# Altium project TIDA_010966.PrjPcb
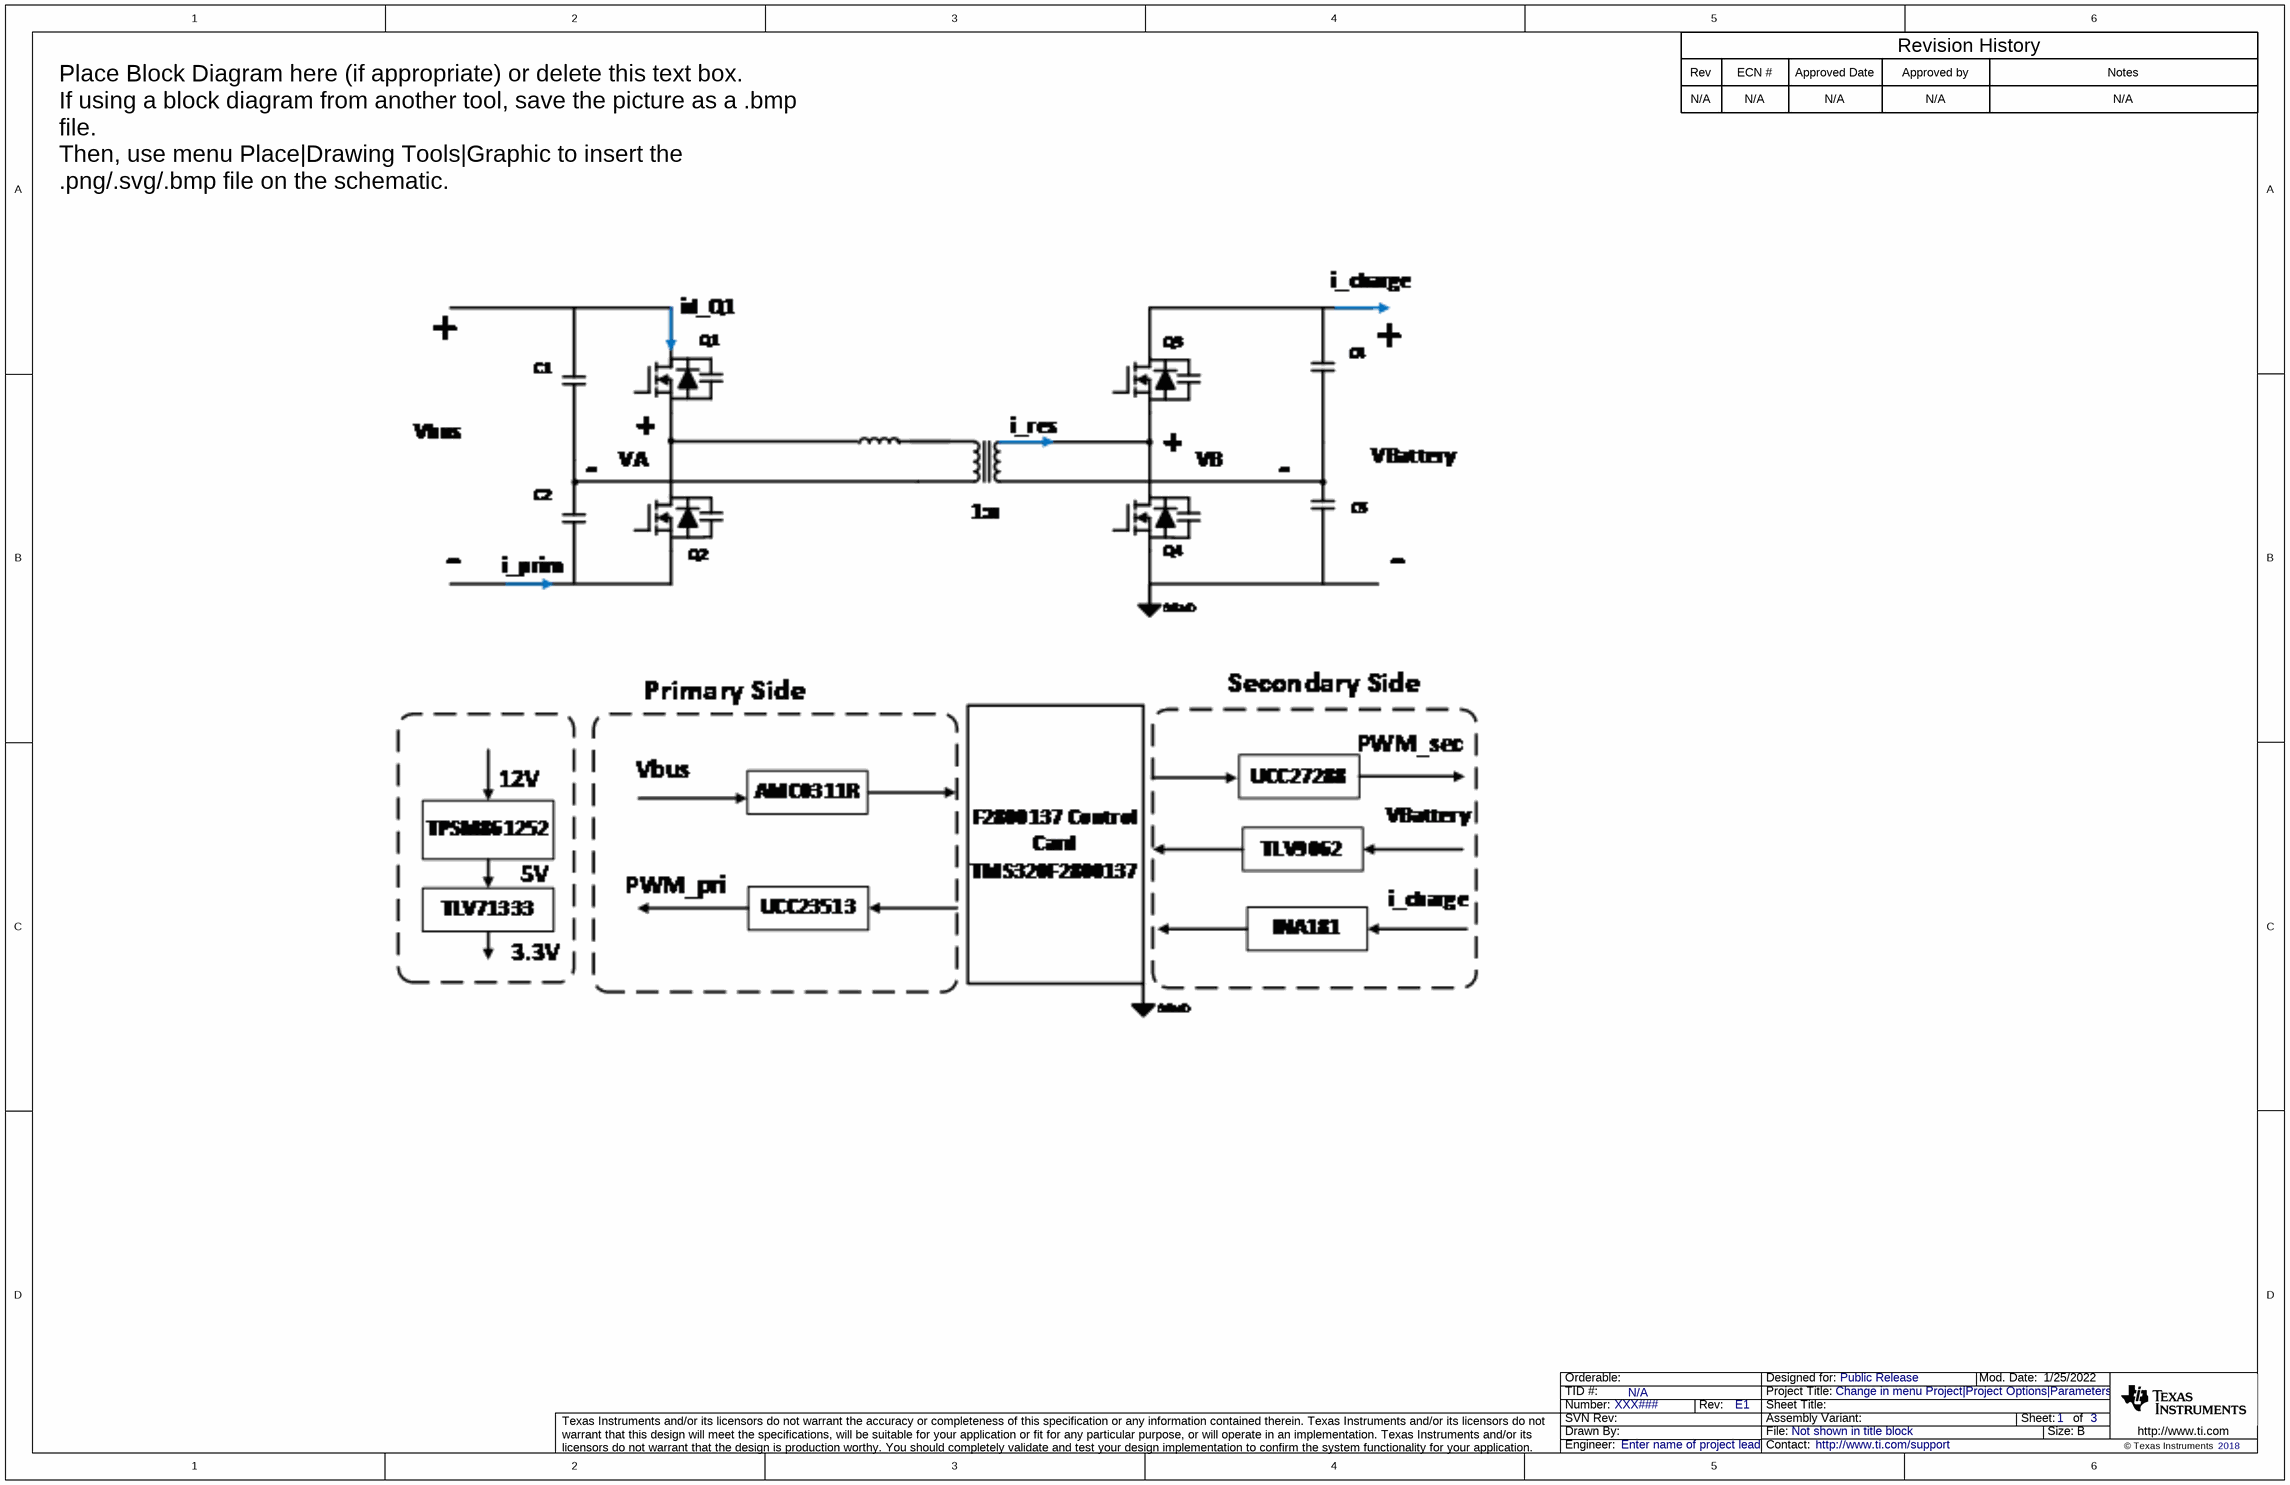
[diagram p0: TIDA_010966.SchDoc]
CopyrightYear: 2018; PCB_Layout: Who did the Layout?; PCB_Rev: E1; PRJ_Customer: Public Release; PRJ_Engineer: Enter name of project lead; PRJ_Number: XXX###; PRJ_Title: Change in menu Project|Project Options|Parameters; SCH_Rev: E1; TechSupport: http://www.ti.com/support; TID: N/A
2 sheets, 120 parts. Net scope: flat (ports and power ports of the same name join across sheets).
Board file: TIDA_010966.PcbDoc
Sheets:
  TIDA_010966.SchDoc
  TIDA_010966_BlankSheet.SchDoc

## Sheet TIDA_010966.SchDoc
size 431 x 279 mm; Date: Not shown in title block; ApprovedBy: Not shown in title block; CheckedBy: Not shown in title block; Author: Not shown in title block; CompanyName: Not shown in title block; Engineer: Not shown in title block; Organization: Not shown in title block; Address1: Not shown in title block; Address2: Not shown in title block; Address3: Not shown in title block; Address4: Not shown in title block; DocumentNumber: 1; Revision: Use project parameter SCH_Rev; SheetNumber: 1; SheetTotal: 3; PageSetup: Record=PageOptions¦CenterHorizontal=True¦CenterVertical=True¦PrintScale=1.00¦XCorrection=1.00¦YCorrection=1.00¦PrintKind=0¦BorderSize=5000000¦LeftOffset=0¦BottomOffset=0¦Orientation=2¦PaperLength=1000¦PaperWidth=1000¦Scale=100¦PaperSource=15¦PrintQuality=600¦MediaType=1¦DitherType=10¦PaperKind=Letter¦PrintScaleMode=1

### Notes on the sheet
- Rev
- N/A
- ECN #
- Approved Date
- Approved by
- Revision History
- Notes
- Place Block Diagram here (if appropriate) or delete this text box.
  If using a block diagram from another tool, save the picture as a .bmp file.
  Then, use menu Place|Drawing Tools|Graphic to insert the .png/.svg/.bmp file on the schematic.

## Sheet TIDA_010966_BlankSheet.SchDoc
size A2; Date: Not shown in title block; ApprovedBy: Not shown in title block; CheckedBy: Not shown in title block; Author: Not shown in title block; CompanyName: Not shown in title block; Engineer: Not shown in title block; Organization: Not shown in title block; Address1: Not shown in title block; Address2: Not shown in title block; Address3: Not shown in title block; Address4: Not shown in title block; DocumentNumber: 2; Revision: Use project parameter SCH_Rev; SheetNumber: 2; SheetTotal: 3; PageSetup: Record=PageOptions¦CenterHorizontal=True¦CenterVertical=True¦PrintScale=1.00¦XCorrection=1.00¦YCorrection=1.00¦PrintKind=0¦BorderSize=5000000¦LeftOffset=0¦BottomOffset=0¦Orientation=2¦PaperLength=1000¦PaperWidth=1000¦Scale=100¦PaperSource=15¦PrintQuality=600¦MediaType=1¦DitherType=10¦PaperKind=Letter¦PrintScaleMode=1
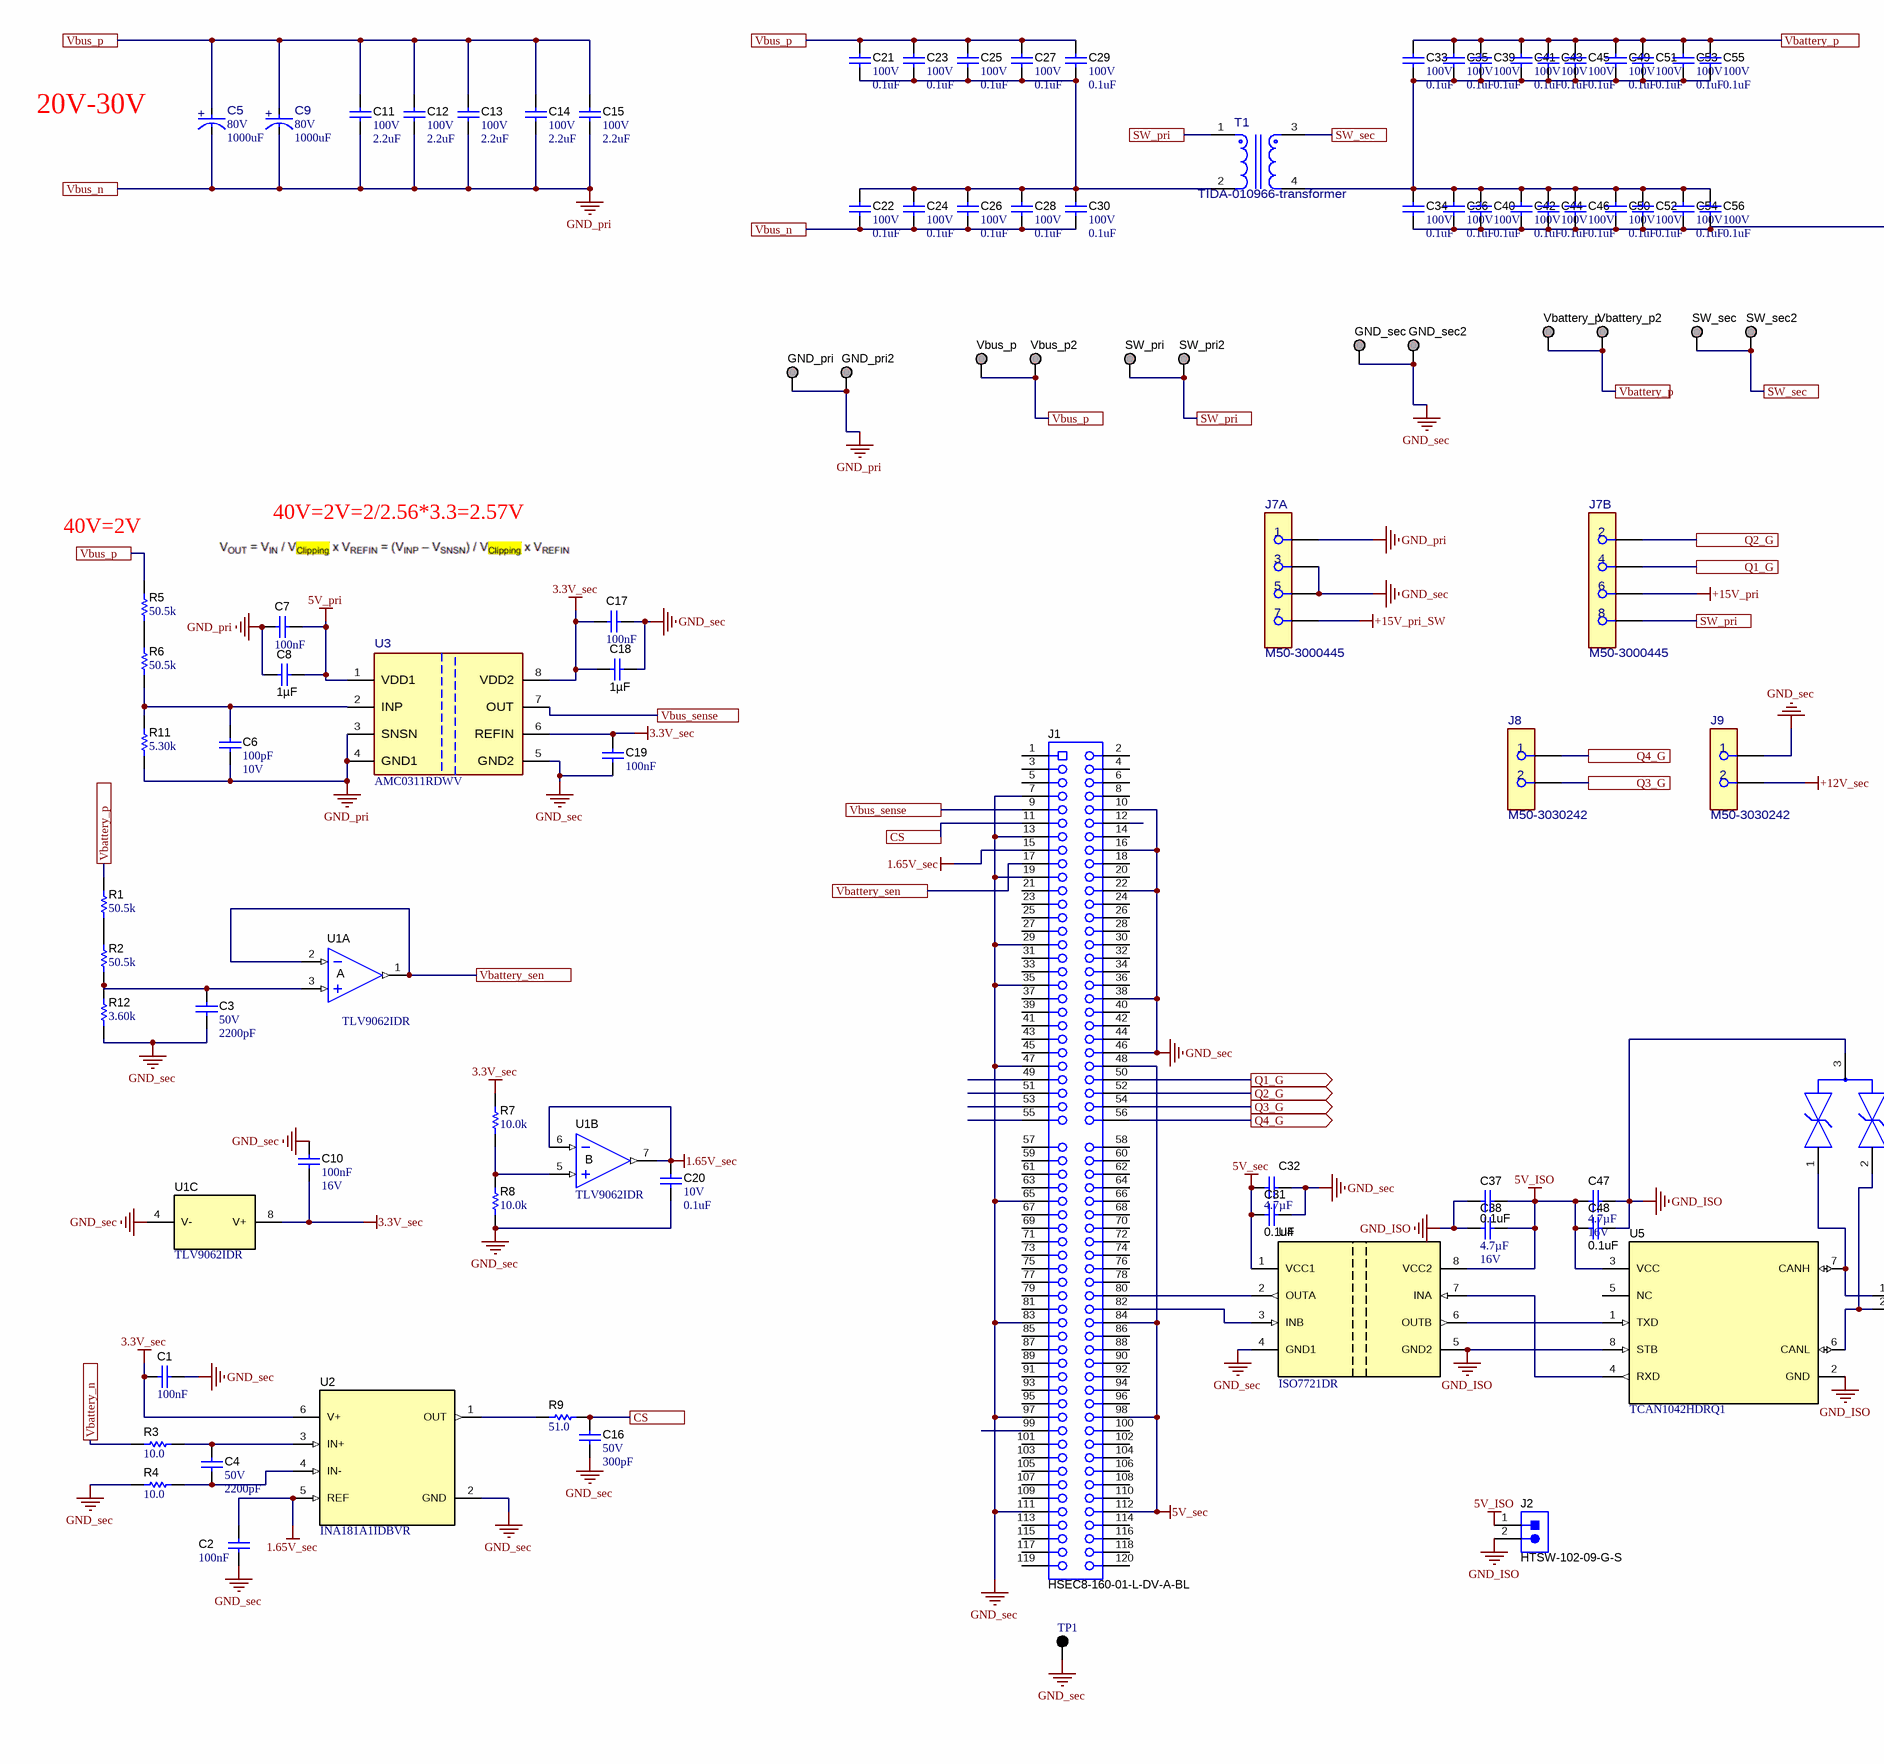
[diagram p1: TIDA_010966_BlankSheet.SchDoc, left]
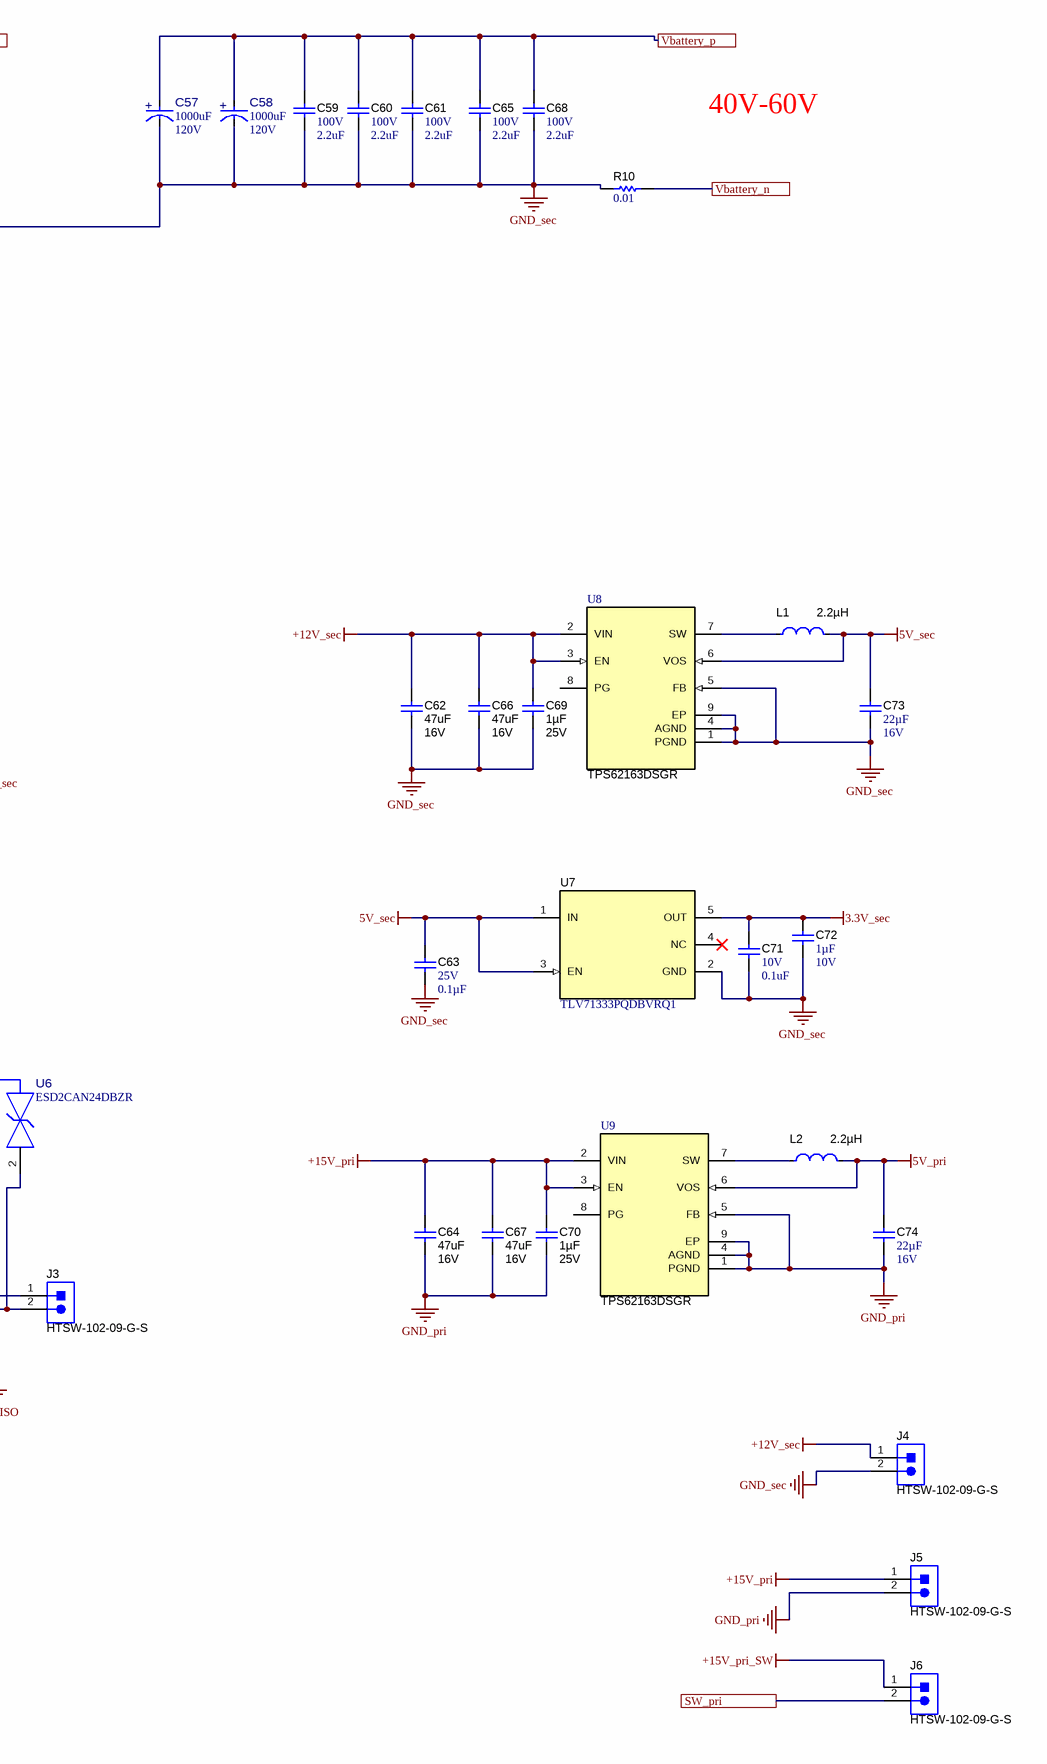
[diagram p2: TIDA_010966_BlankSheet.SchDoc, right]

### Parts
C1  Cap_F: 100nF  [0603]  (hidden comment: CGA3E2X7R1E104K080AA)
C2  ValueDisplayed: 100nF  [0603]  (hidden comment: GRM1885C1H301JA01D)
C3  VDC_V: 50V  ValueDisplayed: 2200pF  [0603]  (hidden comment: GRM1885C1H222JA01D)
C4  VDC_V: 50V  ValueDisplayed: 2200pF  [0603]  (hidden comment: GRM1885C1H222JA01D)
C5  VDC_V: 80V  ValueDisplayed: 1000uF  [FP-EGPD800ELL102ML35H_RADIAL-MFG]  (hidden comment: EGPD800ELL102ML35H)
C6  Cap_F: 100pF  VDC_V: 10V  [0603]  (hidden comment: 0603ZC101KAT2A)
C7  ValueDisplayed: 100nF  [0603]  (hidden comment: GRM1885C1H301JA01D)
C8  Cap_F: 1µF  [0805_HV]  (hidden comment: C0805C105K3RACTU)
C9  VDC_V: 80V  ValueDisplayed: 1000uF  [FP-EGPD800ELL102ML35H_RADIAL-MFG]  (hidden comment: EGPD800ELL102ML35H)
C10  Cap_F: 100nF  VDC_V: 16V  [0603]  (hidden comment: GRM188R71C104KA01D)
C11  VDC_V: 100V  ValueDisplayed: 2.2uF  [1206_180]  (hidden comment: CGA5L3X7S2A225K160AB)
C12  VDC_V: 100V  ValueDisplayed: 2.2uF  [1206_180]  (hidden comment: CGA5L3X7S2A225K160AB)
C13  VDC_V: 100V  ValueDisplayed: 2.2uF  [1206_180]  (hidden comment: CGA5L3X7S2A225K160AB)
C14  VDC_V: 100V  ValueDisplayed: 2.2uF  [1206_180]  (hidden comment: CGA5L3X7S2A225K160AB)
C15  VDC_V: 100V  ValueDisplayed: 2.2uF  [1206_180]  (hidden comment: CGA5L3X7S2A225K160AB)
C16  VDC_V: 50V  ValueDisplayed: 300pF  [0603]  (hidden comment: GRM1885C1H301JA01D)
C17  ValueDisplayed: 100nF  [0603]  (hidden comment: GRM1885C1H301JA01D)
C18  Cap_F: 1µF  [0805_HV]  (hidden comment: C0805C105K3RACTU)
C19  ValueDisplayed: 100nF  [0603]  (hidden comment: GRM1885C1H301JA01D)
C20  VDC_V: 10V  ValueDisplayed: 0.1uF  [0402]  (hidden comment: C1005X5R1A104K050BA)
C21  VDC_V: 100V  ValueDisplayed: 0.1uF  [1206_190]  (hidden comment: C3216C0G2A104J160AC)
C22  VDC_V: 100V  ValueDisplayed: 0.1uF  [1206_190]  (hidden comment: C3216C0G2A104J160AC)
C23  VDC_V: 100V  ValueDisplayed: 0.1uF  [1206_190]  (hidden comment: C3216C0G2A104J160AC)
C24  VDC_V: 100V  ValueDisplayed: 0.1uF  [1206_190]  (hidden comment: C3216C0G2A104J160AC)
C25  VDC_V: 100V  ValueDisplayed: 0.1uF  [1206_190]  (hidden comment: C3216C0G2A104J160AC)
C26  VDC_V: 100V  ValueDisplayed: 0.1uF  [1206_190]  (hidden comment: C3216C0G2A104J160AC)
C27  VDC_V: 100V  ValueDisplayed: 0.1uF  [1206_190]  (hidden comment: C3216C0G2A104J160AC)
C28  VDC_V: 100V  ValueDisplayed: 0.1uF  [1206_190]  (hidden comment: C3216C0G2A104J160AC)
C29  VDC_V: 100V  ValueDisplayed: 0.1uF  [1206_190]  (hidden comment: C3216C0G2A104J160AC)
C30  VDC_V: 100V  ValueDisplayed: 0.1uF  [1206_190]  (hidden comment: C3216C0G2A104J160AC)
C31  ValueDisplayed: 0.1uF  [0402]  (hidden comment: 0402YC104KAT2A)
C32  Cap_F: 4.7µF  [0603]  (hidden comment: GRM188Z71C475KE21D)
C33  VDC_V: 100V  ValueDisplayed: 0.1uF  [1206_190]  (hidden comment: C3216C0G2A104J160AC)
C34  VDC_V: 100V  ValueDisplayed: 0.1uF  [1206_190]  (hidden comment: C3216C0G2A104J160AC)
C35  VDC_V: 100V  ValueDisplayed: 0.1uF  [1206_190]  (hidden comment: C3216C0G2A104J160AC)
C36  VDC_V: 100V  ValueDisplayed: 0.1uF  [1206_190]  (hidden comment: C3216C0G2A104J160AC)
C37  ValueDisplayed: 0.1uF  [0402]  (hidden comment: 0402YC104KAT2A)
C38  Cap_F: 4.7µF  VDC_V: 16V  [0603]  (hidden comment: GRM188Z71C475KE21D)
C39  VDC_V: 100V  ValueDisplayed: 0.1uF  [1206_190]  (hidden comment: C3216C0G2A104J160AC)
C40  VDC_V: 100V  ValueDisplayed: 0.1uF  [1206_190]  (hidden comment: C3216C0G2A104J160AC)
C41  VDC_V: 100V  ValueDisplayed: 0.1uF  [1206_190]  (hidden comment: C3216C0G2A104J160AC)
C42  VDC_V: 100V  ValueDisplayed: 0.1uF  [1206_190]  (hidden comment: C3216C0G2A104J160AC)
C43  VDC_V: 100V  ValueDisplayed: 0.1uF  [1206_190]  (hidden comment: C3216C0G2A104J160AC)
C44  VDC_V: 100V  ValueDisplayed: 0.1uF  [1206_190]  (hidden comment: C3216C0G2A104J160AC)
C45  VDC_V: 100V  ValueDisplayed: 0.1uF  [1206_190]  (hidden comment: C3216C0G2A104J160AC)
C46  VDC_V: 100V  ValueDisplayed: 0.1uF  [1206_190]  (hidden comment: C3216C0G2A104J160AC)
C47  Cap_F: 4.7µF  VDC_V: 16V  [0603]  (hidden comment: GRM188Z71C475KE21D)
C48  ValueDisplayed: 0.1uF  [0402]  (hidden comment: 0402YC104KAT2A)
C49  VDC_V: 100V  ValueDisplayed: 0.1uF  [1206_190]  (hidden comment: C3216C0G2A104J160AC)
C50  VDC_V: 100V  ValueDisplayed: 0.1uF  [1206_190]  (hidden comment: C3216C0G2A104J160AC)
C51  VDC_V: 100V  ValueDisplayed: 0.1uF  [1206_190]  (hidden comment: C3216C0G2A104J160AC)
C52  VDC_V: 100V  ValueDisplayed: 0.1uF  [1206_190]  (hidden comment: C3216C0G2A104J160AC)
C53  VDC_V: 100V  ValueDisplayed: 0.1uF  [1206_190]  (hidden comment: C3216C0G2A104J160AC)
C54  VDC_V: 100V  ValueDisplayed: 0.1uF  [1206_190]  (hidden comment: C3216C0G2A104J160AC)
C55  VDC_V: 100V  ValueDisplayed: 0.1uF  [1206_190]  (hidden comment: C3216C0G2A104J160AC)
C56  VDC_V: 100V  ValueDisplayed: 0.1uF  [1206_190]  (hidden comment: C3216C0G2A104J160AC)
C57  ValueDisplayed: 1000uF  VDC_V: 120V  [FP-EY3A102MNN1850M_RADIAL-MFG]  (hidden comment: EY3A102MNN1850M)
C58  ValueDisplayed: 1000uF  VDC_V: 120V  [FP-EY3A102MNN1850M_RADIAL-MFG]  (hidden comment: EY3A102MNN1850M)
C59  VDC_V: 100V  ValueDisplayed: 2.2uF  [1206_180]  (hidden comment: CGA5L3X7S2A225K160AB)
C60  VDC_V: 100V  ValueDisplayed: 2.2uF  [1206_180]  (hidden comment: CGA5L3X7S2A225K160AB)
C61  VDC_V: 100V  ValueDisplayed: 2.2uF  [1206_180]  (hidden comment: CGA5L3X7S2A225K160AB)
C62  ValueDisplayed: 47uF  Value2: 16V  [1210_270]  (hidden comment: GRM32ER61C476KE15L)
C63  VDC_V: 25V  ValueDisplayed: 0.1µF  [0402]  (hidden comment: CGA2B3X7R1E104K050BB)
C64  ValueDisplayed: 47uF  Value2: 16V  [1210_270]  (hidden comment: GRM32ER61C476KE15L)
C65  VDC_V: 100V  ValueDisplayed: 2.2uF  [1206_180]  (hidden comment: CGA5L3X7S2A225K160AB)
C66  ValueDisplayed: 47uF  Value2: 16V  [1210_270]  (hidden comment: GRM32ER61C476KE15L)
C67  ValueDisplayed: 47uF  Value2: 16V  [1210_270]  (hidden comment: GRM32ER61C476KE15L)
C68  VDC_V: 100V  ValueDisplayed: 2.2uF  [1206_180]  (hidden comment: CGA5L3X7S2A225K160AB)
C69  Cap_F: 1µF  VDC_V: 25V  [0805_HV]  (hidden comment: C0805C105K3RACTU)
C70  Cap_F: 1µF  VDC_V: 25V  [0805_HV]  (hidden comment: C0805C105K3RACTU)
C71  VDC_V: 10V  ValueDisplayed: 0.1uF  [0402]  (hidden comment: C1005X5R1A104K050BA)
C72  Cap_F: 1µF  VDC_V: 10V  [0603]  (hidden comment: GRM188R71A105KA61D)
C73  ValueDisplayed: 22µF  VDC_V: 16V  [0805_HV]  (hidden comment: CL21A226KOQNNNE)
C74  ValueDisplayed: 22µF  VDC_V: 16V  [0805_HV]  (hidden comment: CL21A226KOQNNNE)
GND_pri  0312-0-15-15-34-27-10-0  [Mill-Max_0312-0-15-15-34-27-10-0]  (value not drawn)
GND_pri2  0312-0-15-15-34-27-10-0  [Mill-Max_0312-0-15-15-34-27-10-0]  (value not drawn)
GND_sec  0312-0-15-15-34-27-10-0  [Mill-Max_0312-0-15-15-34-27-10-0]  (value not drawn)
GND_sec2  0312-0-15-15-34-27-10-0  [Mill-Max_0312-0-15-15-34-27-10-0]  (value not drawn)
J1  HSEC8-160-01-L-DV-A-BL  [controlCARD-120HSEC]
J2  HTSW-102-09-G-S  [Samtec_HTSW-102-09-x-S]
J3  HTSW-102-09-G-S  [Samtec_HTSW-102-09-x-S]
J4  HTSW-102-09-G-S  [Samtec_HTSW-102-09-x-S]
J5  HTSW-102-09-G-S  [Samtec_HTSW-102-09-x-S]
J6  HTSW-102-09-G-S  [Samtec_HTSW-102-09-x-S]
J7  M50-3000445  [FP-M50-3000445_CONN_SCKT_STRP8-MFG]  (parts A,B of 2)
J8  M50-3030242  [FP-M50-3030242_HDR2-MFG]
J9  M50-3030242  [FP-M50-3030242_HDR2-MFG]
L1  Ind_H: 2.2µH  [FP-74438336010_SMD2-MFG]  (hidden comment: 74438336022)
L2  Ind_H: 2.2µH  [FP-74438336010_SMD2-MFG]  (hidden comment: 74438336022)
R1  ValueDisplayed: 50.5k  [0805_HV]  (hidden comment: RT0805BRD0750K5L)
R2  ValueDisplayed: 50.5k  [0805_HV]  (hidden comment: RT0805BRD0750K5L)
R3  ValueDisplayed: 10.0  [0603]  (hidden comment: RNCF0603AKT10R0)
R4  ValueDisplayed: 10.0  [0603]  (hidden comment: RNCF0603AKT10R0)
R5  ValueDisplayed: 50.5k  [0805_HV]  (hidden comment: RT0805BRD0750K5L)
R6  ValueDisplayed: 50.5k  [0805_HV]  (hidden comment: RT0805BRD0750K5L)
R7  ValueDisplayed: 10.0k  [0805_HV]  (hidden comment: PLTT0805Z1002QGT5)
R8  ValueDisplayed: 10.0k  [0805_HV]  (hidden comment: PLTT0805Z1002QGT5)
R9  ValueDisplayed: 51.0  [0603]  (hidden comment: RC0603FR-0751RL)
R10  ValueDisplayed: 0.01  [2512]  (hidden comment: LRMAP2512-R01FT4)
R11  ValueDisplayed: 5.30k  [0805_HV]  (hidden comment: RT0805BRD075K3L)
R12  ValueDisplayed: 3.60k  [0805_HV]  (hidden comment: RG2012P-362-B-T5)
SW_pri  0312-0-15-15-34-27-10-0  [Mill-Max_0312-0-15-15-34-27-10-0]  (value not drawn)
SW_pri2  0312-0-15-15-34-27-10-0  [Mill-Max_0312-0-15-15-34-27-10-0]  (value not drawn)
SW_sec  0312-0-15-15-34-27-10-0  [Mill-Max_0312-0-15-15-34-27-10-0]  (value not drawn)
SW_sec2  0312-0-15-15-34-27-10-0  [Mill-Max_0312-0-15-15-34-27-10-0]  (value not drawn)
T1  TIDA-010966-transformer  [FP-PMP41134_transformer_PTH-MFG]
TP1  5011  [Keystone5011]  (value not drawn)
U1  TLV9062IDR  [D0008A_N]  (parts A,B,C of 3)
U2  INA181A1IDBVR  [DBV0006A_N]
U3  AMC0311RDWV  [DWV0008A-MFG]
U4  ISO7721DR  [D0008B_HV]
U5  TCAN1042HDRQ1  [D0008A_L]
U6  ESD2CAN24DBZR  [DBZ0003A-MFG]
U7  TLV71333PQDBVRQ1  [DBV0005A_N]
U8  TPS62163DSGR  [DSG0008A]
U9  TPS62163DSGR  [DSG0008A]
Vbattery_p  0312-0-15-15-34-27-10-0  [Mill-Max_0312-0-15-15-34-27-10-0]  (value not drawn)
Vbattery_p2  0312-0-15-15-34-27-10-0  [Mill-Max_0312-0-15-15-34-27-10-0]  (value not drawn)
Vbus_p  0312-0-15-15-34-27-10-0  [Mill-Max_0312-0-15-15-34-27-10-0]  (value not drawn)
Vbus_p2  0312-0-15-15-34-27-10-0  [Mill-Max_0312-0-15-15-34-27-10-0]  (value not drawn)

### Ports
CS, Q1_G, Q1_G (out), Q2_G, Q2_G (out), Q3_G, Q3_G (out), Q4_G, Q4_G (out), SW_pri, SW_sec, Vbattery_n, Vbattery_p, Vbattery_sen, Vbus_n, Vbus_p, Vbus_sense

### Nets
1.65V_sec: C2.1 C20.1 J1.15 U1.6(IN-) U1.7(OUT) U2.5(REF)
3.3V_sec: C1.1 C10.2 C17.2 C18.1 C19.2 C71.1 C72.1 R7.2 U1.8(V+) U2.6(V+) U3.6(REFIN) U3.8(VDD2) U7.5(OUT)
5V_ISO: C37.2 C38.2 C47.1 C48.1 J2.1 U4.8(VCC2) U5.3(VCC)
5V_pri: C7.1 C8.2 C74.1 L2.2 U3.1(VDD1) U9.6(VOS)
5V_sec: C31.2 C32.2 C63.1 C73.1 J1.48 J1.84 J1.98 J1.112 L1.2 U4.1(VCC1) U7.1(IN) U7.3(EN) U8.6(VOS)
+12V_sec: C62.2 C66.2 C69.1 J4.1 J9.2 U8.2(VIN) U8.3(EN)
+15V_pri: C64.2 C67.2 C70.1 J5.1 J7.6 U9.2(VIN) U9.3(EN)
+15V_pri_SW: J6.1 J7.7
GND_ISO: C37.1 C38.1 C47.2 C48.2 J2.2 U4.5(GND2) U5.2(GND) U5.8(STB) U6.3(GND)
GND_pri: C5.1(CATHODE) C6.2 C7.2 C8.1 C9.1(CATHODE) C11.2 C12.2 C13.2 C14.2 C15.2 C22.2 C24.2 C26.2 C28.2 C30.2 C64.1 C67.1 C70.2 C74.2 GND_pri.1 GND_pri2.1 J5.2 J7.1 R11.1 U3.3(SNSN) U3.4(GND1) U9.1(PGND) U9.4(AGND) U9.5(FB) U9.9(EP) ; port Vbus_n
GND_sec: C1.2 C2.2 C3.2 C10.1 C16.2 C17.1 C18.2 C19.1 C20.2 C31.1 C32.1 C34.2 C36.2 C40.2 C42.2 C44.2 C46.2 C50.2 C52.2 C54.2 C56.2 C57.1(CATHODE) C58.1(CATHODE) C59.2 C60.2 C61.2 C62.1 C63.2 C65.2 C66.1 C68.2 C69.2 C71.2 C72.2 C73.2 GND_sec.1 GND_sec2.1 J1.7 J1.10 J1.13 J1.16 J1.19 J1.22 J1.29 J1.35 J1.38 J1.46 J1.47 J1.65 J1.83 J1.97 J1.111 J4.2 J7.3 J7.5 J9.1 R4.1 R8.1 R10.1 R12.1 TP1.1 U1.4(V-) U2.2(GND) U3.5(GND2) U4.4(GND1) U7.2(GND) U8.1(PGND) U8.4(AGND) U8.5(FB) U8.9(EP)
CS: C16.1 J1.11 R9.2 ; port CS
Q1_G: J1.50 J7.4 ; port Q1_G
Q2_G: J1.52 J7.2 ; port Q2_G
Q3_G: J1.54 J8.2 ; port Q3_G
Q4_G: J1.56 J8.1 ; port Q4_G
SW_pri: J6.2 J7.8 SW_pri.1 SW_pri2.1 T1.1 ; port SW_pri
SW_sec: SW_sec.1 SW_sec2.1 T1.3 ; port SW_sec
Vbattery_n: R3.1 R10.2 ; port Vbattery_n
Vbattery_p: C33.1 C35.1 C39.1 C41.1 C43.1 C45.1 C49.1 C51.1 C53.1 C55.1 C57.2(ANODE) C58.2(ANODE) C59.1 C60.1 C61.1 C65.1 C68.1 R1.2 Vbattery_p.1 Vbattery_p2.1 ; port Vbattery_p
Vbattery_sen: J1.17 U1.1(OUT) U1.2(IN-) ; port Vbattery_sen
Vbus_p: C5.2(ANODE) C9.2(ANODE) C11.1 C12.1 C13.1 C14.1 C15.1 C21.1 C23.1 C25.1 C27.1 C29.1 R5.2 Vbus_p.1 Vbus_p2.1 ; port Vbus_p
Vbus_sense: J1.9 U3.7(OUT) ; port Vbus_sense
NetC3_1: C3.1 R2.1 R12.2 U1.3(IN+)
NetC4_1: C4.1 R3.2 U2.3(IN+)
NetC4_2: C4.2 R4.2 U2.4(IN-)
NetC6_1: C6.1 R6.1 R11.2 U3.2(INP)
NetC21_2: C21.2 C22.1 C23.2 C24.1 C25.2 C26.1 C27.2 C28.1 C29.2 C30.1 T1.2
NetC33_2: C33.2 C34.1 C35.2 C36.1 C39.2 C40.1 C41.2 C42.1 C43.2 C44.1 C45.2 C46.1 C49.2 C50.1 C51.2 C52.1 C53.2 C54.1 C55.2 C56.1 T1.4
NetJ1_80: J1.80 U4.2(OUTA)
NetJ1_82: J1.82 U4.3(INB)
NetJ3_1: J3.1 U5.7(CANH) U6.1(1_IO)
NetJ3_2: J3.2 U5.6(CANL) U6.2(2_IO)
NetL1_1: L1.1 U8.7(SW)
NetL2_1: L2.1 U9.7(SW)
NetR1_1: R1.1 R2.2
NetR5_1: R5.1 R6.2
NetR7_1: R7.1 R8.2 U1.5(IN+)
NetR9_1: R9.1 U2.1(OUT)
NetU4_6: U4.6(OUTB) U5.1(TXD)
NetU4_7: U4.7(INA) U5.4(RXD)

Not connected (* = marked no-connect by the designer): J1 1 2 3 4 5 6 8 12 14 18 20 21 23 24 25 26 27 28 30 31 32 33 34 36 37 39 40 41 42 43 44 45 49 51 53 55 57 58 59 60 61 62 63 64 66 67 68 69 70 71 72 73 74 75 76 77 78 79 81 85 86 87 88 89 90 91 92 93 94 95 96 99 100 101 102 103 104 105 106 107 108 109 110 113 114 115 116 117 118 119 120; U5 5(NC); U7 4(NC)*; U8 8(PG); U9 8(PG)

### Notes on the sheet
- 20V-30V
- 40V-60V
- 40V=2V=2/2.56*3.3=2.57V
- 40V=2V

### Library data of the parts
C1 = CMP-0007077-5: CAP, CERM, 0.1 uF, 25 V, +/- 10%, X7R, AEC-Q200 Grade 1, 0603; Manufacturer: TDK; TaMin_C: -55°C; Polarized: N; SizeAreaWB_mm2: 4.68; Value1: Unknown; U/M: EA; Value: 0.1uF; TaMax_C: 125°C; SizeZ_mm: 1; SizeX_mm: 1.6; SizeY_mm: 0.8; Value2: 25V; SizeArea_mm2: 1.28; AEC Qualified: Y; AEC Category: Q200
C2 C7 C17 C19 = CMP-0007206-4: CAP, CERM, 300 pF, 50 V, +/- 5%, C0G/NP0, 0603; Manufacturer: MuRata; TaMin_C: -55°C; Polarized: N; SizeAreaWB_mm2: 4.68; Value1: Unknown; U/M: EA; Value: 300pF; TaMax_C: 125°C; SizeZ_mm: 1; SizeX_mm: 1.6; SizeY_mm: 0.8; Value2: 50V; SizeArea_mm2: 1.28; AEC Category: Q200
C3 C4 = CMP-0007198-4: CAP, CERM, 2200 pF, 50 V, +/- 5%, C0G/NP0, 0603; Manufacturer: MuRata; TaMin_C: -55°C; Polarized: N; SizeAreaWB_mm2: 4.68; Value1: Unknown; U/M: EA; Value: 2200pF; TaMax_C: 125°C; SizeZ_mm: 1; SizeX_mm: 1.6; SizeY_mm: 0.8; SizeArea_mm2: 1.28; Cap_F: 2.2nF; AEC Category: Q200
C5 C9 = CMP-0097417-1: 1000 µF 80 V Aluminum Electrolytic Capacitors Radial, Can 27mOhm @ 100kHz 2000 Hrs @ 135°C; Manufacturer: United Chemi-Con; AEC Grade: Grade 0; Value: 1mF; Leakage Current: 2400uA; AEC Qualified: Yes; IRMS_A: 4.59A; Tolerance_%: 20%; Dissipation Factor: 8%; Life: 2000Hours; SizeZ_mm: 36.5mm; Esr: 27m
C6 = CMP-0006812-4: CAP, CERM, 100 pF, 10 V, +/- 10%, X7R, 0603; Manufacturer: AVX; TaMin_C: -55°C; Polarized: N; SizeAreaWB_mm2: 4.68; Value1: Unknown; U/M: EA; Value: 100pF; TaMax_C: 125°C; SizeZ_mm: 1; SizeX_mm: 1.6; SizeY_mm: 0.8; SizeArea_mm2: 1.28; AEC Category: Q200
C8 C18 = CMP-0007728-2: CAP, CERM, 1 uF, 25 V, +/- 10%, X7R, 0805; Manufacturer: Kemet; TaMin_C: -55°C; Polarized: N; SizeAreaWB_mm2: 6.75; Value1: Unknown; U/M: EA; Value: 1uF; TaMax_C: 125°C; SizeZ_mm: 1.45; SizeX_mm: 2; SizeY_mm: 1.25; Cap_Case: 0805; Value2: 25V; SizeArea_mm2: 2.5; AEC Category: Q200
C10 = CMP-0007378-5: CAP, CERM, 0.1 uF, 16 V, +/- 10%, X7R, 0603; Manufacturer: MuRata; TaMin_C: -55°C; Polarized: N; SizeAreaWB_mm2: 4.68; Value1: Unknown; U/M: EA; Value: 0.1uF; TaMax_C: 125°C; SizeZ_mm: 1; SizeX_mm: 1.6; SizeY_mm: 0.8; SizeArea_mm2: 1.28; AEC Category: Q200
C11-C15 C59-C61 C65 C68 = CMP-0008790-2: CAP, CERM, 2.2 uF, 100 V, +/- 10%, X7S, AEC-Q200 Grade 1, 1206; Manufacturer: TDK; TaMin_C: -55°C; ESR_ohm: 5.718m; Polarized: N; SizeAreaWB_mm2: 10.92; Value1: 0.005718 ohm; U/M: EA; Value: 2.2uF; TaMax_C: 125°C; SizeZ_mm: 1.8; SizeX_mm: 3.2; SizeY_mm: 1.6; SizeArea_mm2: 5.12; AEC Qualified: Y; Cap_F: 2.2µF; IRMS_A: 3.03632A; AEC Grade: 1; AEC Category: Q200
C16 = CMP-0007206-4: CAP, CERM, 300 pF, 50 V, +/- 5%, C0G/NP0, 0603; Manufacturer: MuRata; TaMin_C: -55°C; Polarized: N; SizeAreaWB_mm2: 4.68; Value1: Unknown; U/M: EA; Value: 300pF; TaMax_C: 125°C; SizeZ_mm: 1; SizeX_mm: 1.6; SizeY_mm: 0.8; SizeArea_mm2: 1.28; AEC Category: Q200
C20 C71 = CMP-0006259-2: CAP, CERM, 0.1 uF, 10 V, +/- 10%, X5R, 0402; Manufacturer: TDK; TaMin_C: -55°C; Polarized: N; SizeAreaWB_mm2: 3; Value1: Unknown; U/M: EA; Value: 0.1uF; TaMax_C: 85°C; SizeZ_mm: 0.6; SizeX_mm: 1; SizeY_mm: 0.5; Cap_F: 100nF; AEC Category: Q200
C21-C30 C33-C36 C39-C46 C49-C56 = CMP-0008643-2: CAP, CERM, 0.1 uF, 100 V, +/- 5%, C0G/NP0, 1206_190; Manufacturer: TDK; TaMin_C: -55°C; Polarized: N; SizeAreaWB_mm2: 10.92; Value1: Unknown; U/M: EA; Value: 0.1uF; TaMax_C: 125°C; SizeZ_mm: 1.9; SizeX_mm: 3.2; SizeY_mm: 1.6; Cap_Case: 1206; SizeArea_mm2: 5.12; Cap_F: 100nF; AEC Category: Q200
C31 C37 C48 = CMP-0006201-2: CAP, CERM, 0.1 uF, 16 V, +/- 10%, X7R, 0402; Manufacturer: AVX; Polarized: N; Value: 0.1uF; U/M: EA; Cap_F: 100nF; Value1: Unknown; VDC_V: 16V; TaMin_C: -55°C; TaMax_C: 125°C; SizeArea_mm2: 0.5; SizeAreaWB_mm2: 3; SizeX_mm: 1; SizeZ_mm: 0.6; AEC Category: Q200
C32 = CMP-0064936-4: CAP, CERM, 4.7 uF, 16 V,+/- 10%, X7R, 0603; Manufacturer: MuRata; TaMin_C: -55°C; Polarized: N; SizeAreaWB_mm2: 4.68; Value1: Unknown; U/M: EA; Value: 4.7uF; TaMax_C: 125°C; SizeZ_mm: 1; SizeX_mm: 1.6; SizeY_mm: 0.8; Value2: 16V; SizeArea_mm2: 1.28; AEC Category: Q200
C38 C47 = CMP-0064936-4: CAP, CERM, 4.7 uF, 16 V,+/- 10%, X7R, 0603; Manufacturer: MuRata; TaMin_C: -55°C; Polarized: N; SizeAreaWB_mm2: 4.68; Value1: Unknown; U/M: EA; Value: 4.7uF; TaMax_C: 125°C; SizeZ_mm: 1; SizeX_mm: 1.6; SizeY_mm: 0.8; SizeArea_mm2: 1.28; AEC Category: Q200
C57 C58 = CMP-0122297-1: 1000 µF 120 V Aluminum Electrolytic Capacitors Radial, Can 10000 Hrs @ 105°C; Manufacturer: Chinsan; AEC Qualified: No; Cap_F: 1mF; IRMS_A: 2.4A; SizeZ_mm: 51.5mm; Tolerance_%: 20%; Leakage Current: 1200uA; Life: 10000Hours; Value: 1mF
C62 C64 C66 C67 = CMP-0009211-2: CAP, CERM, 47 uF, 16 V, +/- 10%, X5R, 1210; Manufacturer: MuRata; Polarized: N; Value: 47uF; U/M: EA; Cap_F: 47µF; Value1: Unknown; TaMin_C: -55°C; TaMax_C: 85°C; Cap_Case: 1210; SizeArea_mm2: 8; SizeAreaWB_mm2: 14.7; SizeX_mm: 3.2; SizeY_mm: 2.5; SizeZ_mm: 2.7; AEC Category: Q200
C63 = CMP-0080610-1: CAP, CERM, 0.1 µF, 25 V,+/- 10%, X7R, AEC-Q200 Grade 1, 0402; Manufacturer: TDK; TaMin_C: -55°C; Polarized: N; SizeAreaWB_mm2: 3; U/M: EA; Value: 0.1uF; TaMax_C: 125°C; SizeZ_mm: 0.6; SizeX_mm: 1; SizeY_mm: 0.5; AEC Qualified: Y; Cap_F: 100nF; AEC Category: Q200
C69 C70 = CMP-0007728-2: CAP, CERM, 1 uF, 25 V, +/- 10%, X7R, 0805; Manufacturer: Kemet; TaMin_C: -55°C; Polarized: N; SizeAreaWB_mm2: 6.75; Value1: Unknown; U/M: EA; Value: 1uF; TaMax_C: 125°C; SizeZ_mm: 1.45; SizeX_mm: 2; SizeY_mm: 1.25; Cap_Case: 0805; SizeArea_mm2: 2.5; AEC Category: Q200
C72 = CMP-0007365-1: CAP, CERM, 1 uF, 10 V, +/- 10%, X7R, 0603; Manufacturer: MuRata; TaMin_C: -55°C; ESR_ohm: 11m; Polarized: N; SizeAreaWB_mm2: 4.68; Value1: 0.011 ohm; U/M: EA; Value: 1uF; TaMax_C: 125°C; SizeZ_mm: 1; SizeX_mm: 1.6; SizeY_mm: 0.8; SizeArea_mm2: 1.28; AEC Category: Q200
C73 C74 = CMP-0085852-1: CAP, CERM, 22 µF, 16 V,+/- 10%, X5R, 0805; Manufacturer: Samsung Electro-Mechanics; SizeX_mm: 2; TaMax_C: 85°C; AEC Category: Q200; SizeY_mm: 1.25; TaMin_C: -55°C; SizeZ_mm: 1.45; U/M: EA; Polarized: N; SizeArea_mm2: 2.5; Cap_Case: 0805; SizeAreaWB_mm2: 6.75; Value: 22uF
GND_pri GND_pri2 GND_sec GND_sec2 SW_pri SW_pri2 SW_sec SW_sec2 Vbattery_p Vbattery_p2 Vbus_p Vbus_p2 = CMP-0055026-1: Manufacturer: Mill-Max; CNHeader: FALSE; Green_Lifecycle: Active; Gender: Female; Green_REACh: Passed; CompType: Pin Receptacle; ContactFinish: Gold
J1 = CMP-0003814-2: C2000 controlCARD-120HSEC connector, SMT; Manufacturer: Samtec; Note: The pin numbering does not match Samtec datasheet
J2-J6 = CMP-0075626-1: Header, 100mil, 2x1, Gold, TH; Manufacturer: Samtec; Pitch_mm: 2.54; Gender: Male; Cert_CSA: Y; CT: False; Row_Count: 1
J7 = CMP-0097755-1: Conn Socket Strip SKT 8 POS 1.27mm Solder ST Thru-Hole; Manufacturer: Harwin; Conn Orientation: Vertical; Conn Gender: Female; Current_A: 1A; AEC Qualified: No; Is Female: yes; ContactFinish: Gold,Nickel; SizeZ_mm: 4.55mm; Row_Count: 2
J8 J9 = CMP-0097274-1: 2 Position Receptacle Connector 0.050" (1.27mm) Through Hole Gold; Manufacturer: Harwin; ContactFinish: Gold,Nickel; Current_A: 1A; Is Female: yes; AEC Qualified: No; Row_Count: 1; Conn Gender: Female; Conn Orientation: Vertical; SizeZ_mm: 4.55mm
L1 L2 = CMP-0087867-1: 2.2µH Shielded Molded Inductor 2.4A 67mOhm Max 2-SMD; Manufacturer: Wurth Electronics; SizeZ_mm: 2mm; Material: Metal Composite; Isat: 4.3A; Symbol Name: SYM-74438336010; DCR_ohm: 0.032; AEC Grade: Grade 1; AEC Qualified: Yes
R1 R2 R5 R6 = CMP-0020148-1: RES, 50.5 k, 0.1%, 0.125 W, 0805; Manufacturer: Yageo America; Power_W: 125mW; TempCo: 25 ppm/C; Value_Code: 50k5; U/M: EA; Value: 50.5k; EIA_Code: E192; SizeX_mm: 2; SizeY_mm: 1.25; SizeZ_mm: 1.45; Value2: 0.125W; SizeArea_mm2: 2.5; VDC_V: 150V; AEC Category: Q200
R3 R4 = CMP-0023625-2: RES, 10.0, 0.05%, 0.1 W, 0603; Manufacturer: Stackpole Electronics Inc; Power_W: 100mW; TempCo: 10 ppm/C; Value_Code: 10R0; U/M: EA; Value: 10.0; Res_ohm: 10; SizeX_mm: 1.6; SizeY_mm: 0.8; SizeZ_mm: 1; Value2: 0.1W; SizeArea_mm2: 1.28; VDC_V: 50V; AEC Category: Q200
R7 R8 = CMP-0018847-1: RES, 10.0 k, 0.02%, 0.25 W, 0805; Manufacturer: Vishay-Dale; Power_W: 250mW; TempCo: 5 ppm/C; Value_Code: 10k0; U/M: EA; Value: 10.0k; Res_ohm: 10k; SizeX_mm: 2; SizeY_mm: 1.25; SizeZ_mm: 1.45; Value2: 0.25W; SizeArea_mm2: 2.5; AEC Category: Q200
R9 = CMP-0023169-5: RES, 51.0, 1%, 0.1 W, 0603; Manufacturer: Yageo; Power_W: 100mW; TempCo: 100 ppm/C; Value_Code: 51R0; Value: 51.0; Res_ohm: 51; SizeX_mm: 1.6; SizeY_mm: 0.8; SizeZ_mm: 1; Value2: 0.1W; SizeArea_mm2: 1.28; AEC Qualified: N; VDC_V: 75V; AEC Category: Q200; SizeAreaWB_mm2: 4.68
R10 = CMP-0078925-1: RES, 0.01, 1%, 3 W, AEC-Q200 Grade 0, 2512; Manufacturer: TT Electronics/IRC; Value_Code: R010; SizeArea_mm2: 20.16; AEC Qualified: Y; AEC Category: Q200; Value: 0.01; SizeZ_mm: 0.71; EIA_Code: E96; TempCo: 50 ppm/C; AEC Grade: 0; SizeY_mm: 3.2; Power_W: 3W; SizeX_mm: 6.3
R11 = CMP-0020211-1: RES, 5.30 k, 0.1%, 0.125 W, 0805; Manufacturer: Yageo America; Power_W: 125mW; TempCo: 25 ppm/C; Value_Code: 5k30; U/M: EA; Value: 5.30k; EIA_Code: E192; Res_ohm: 5.3k; SizeX_mm: 2; SizeY_mm: 1.25; SizeZ_mm: 1.45; Value2: 0.125W; SizeArea_mm2: 2.5; VDC_V: 150V; AEC Category: Q200
R12 = CMP-0018966-2: RES, 3.60 k, 0.1%, 0.125 W, 0805; Manufacturer: Susumu Co Ltd; Power_W: 125mW; TempCo: 25 ppm/C; Value_Code: 3k60; U/M: EA; Value: 3.60k; Res_ohm: 3.6k; SizeX_mm: 2; SizeY_mm: 1.25; SizeZ_mm: 1.45; Value2: 0.125W; SizeArea_mm2: 2.5; VDC_V: 100V; AEC Category: Q200
T1 = CMP-0123505-1: TRANSFORMER; Manufacturer: 3L; PartNumber: PMP41134_transformer; Ind_H: 212.4µH; SizeZ_mm: 33.5mm; AEC Qualified: No
TP1 = CMP-0055148-2: Test Point, Multipurpose, Black, TH; Manufacturer: Keystone Electronics; CNHeader: FALSE; ContactFinish: Silver; Green_REACh: Passed; Green_Lifecycle: Active; CT: TRUE
U1 = CMP-0013007-4: 10-MHz, Low-Noise, RRIO, CMOS Operational Amplifier for Cost-Sensitive Systems, D0008A (SOIC-8); Manufacturer: Texas Instruments; SizeX_mm: 4.9; SizeY_mm: 6.2; CompType: IC; SizeZ_mm: 1.75; SizeArea_mm2: 30.38; SizeAreaWB_mm2: 56.58; AEC Category: Q200; AEC Qualified: N; Rating: Catalog
U2 = CMP-0013230-2: Bidirectional, Low- and High-Side Measurement, Multichannel, Voltage Output, Current-Sense Amplifier, DBV0006A (SOT-6); Manufacturer: Texas Instruments; Alternate PartNumber: INA181A1IDBVT; SizeX_mm: 2.8; SizeY_mm: 2.9; CompType: IC; SizeZ_mm: 1.45; SizeArea_mm2: 8.12; SizeAreaWB_mm2: 14.82; U/M: EA
U3 = CMP-0124048-1: Precision, 2.25V Input, Basic and Reinforced Isolated Amplifiers With Single-Ended, Ratiometric Output; Manufacturer: Texas Instruments; SizeZ_mm: 2.8mm; AEC Qualified: No; Bandwidth: 110kHz; Input Bias Current: 3.5nA; Input Offset Voltage: 0.2mV; Max Supply Voltage: 5.5V; Min Supply Voltage: 3V; Number Of Channels: 1; Output Current Per Channel: 14mA; Response Time: 50us; Standoff Height: 0.36mm; TaMax_C: +125°C; TaMin_C: -40°C; TJmax_C: +150°C
U4 = CMP-0076059-2: High Speed, Robust EMC Dual-Channel Digital Isolator, D0008B (SOIC-8); Manufacturer: Texas Instruments; SizeY_mm: 4.9; SizeArea_mm2: 29.4; Rating: Catalog; CompType: IC; AEC Category: Q200; AEC Qualified: N; SizeZ_mm: 1.75; SizeAreaWB_mm2: 55.2; SizeX_mm: 6.0
U5 = CMP-0075990-1: Automotive Fault Protected CAN Transceiver With Flexible Data-Rate, D0008A (SOIC-8); Manufacturer: Texas Instruments; Alternate PartNumber: TCAN1042HDQ1; SizeAreaWB_mm2: 56.58; SizeArea_mm2: 30.38; SizeZ_mm: 1.75; SizeY_mm: 6.2; U/M: EA; CompType: IC; SizeX_mm: 4.9
U6 = CMP-0093261-1: 24-V, 2-Channel ESD Protection Diode for In-Vehicle Networks; Manufacturer: Texas Instruments; Cap_F: 3pF; Breakdown Voltage: 25.5V; Clamping Voltage: 32V; TaMax_C: +150°C; Direction: Bidirectional; TaMin_C: -55°C; Ipp: 3.5A; VRWM: 24V; Standoff Height: 0.01mm; SizeZ_mm: 1.12mm; Ppk: 147W; AEC Qualified: No; Number Of Channels: 2
U7 = CMP-0073750-1: Capacitor-Free, 150-mA, LDO Regulator w/ Foldback Current Limit, DBV0005A (SOT-23-5); Alternate Manufacturer: Texas Instruments; SizeAreaWB_mm2: 14.82; U/M: EA; SizeZ_mm: 1.45; SizeX_mm: 2.8; SizeY_mm: 2.9; SizeArea_mm2: 8.12; CompType: IC
U8 U9 = CMP-0037791-2: Buck Step Down Regulator with 3 to 17 V Input and 5 V Output, -40 to 85 degC, 8-Pin WSON (DSG), Green (RoHS & no Sb/Br); Manufacturer: Texas Instruments; Vin(Min)(V): 3; Switch Current Limit(Typ)(A): 1.8; Vin(Max)(V): 17; Rating: Catalog; Vout(Min)(V): 5; Regulated Outputs(#): 1; Duty Cycle(Max)(%): 100; SubFamily: Step-Down Regulator; Synchronous Rectification: TRUE; Iq(Typ)(mA): 0.017

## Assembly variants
001: not fitted FID1 FID2 FID3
